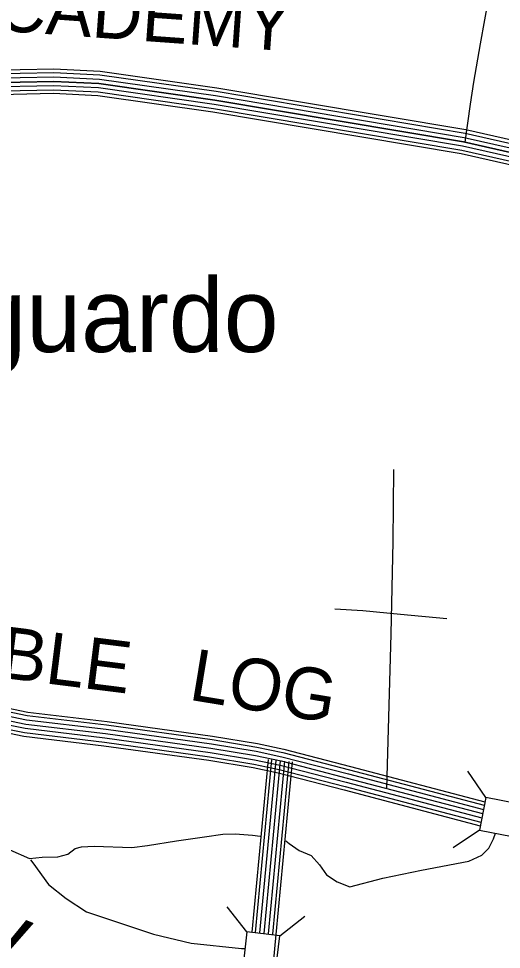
# Model space of a CAD drawing. Extents: x 1788175 to 1969470, y 584502 to 738744.
# Drawn here: x 1840728 to 1844183, y 706761 to 713422 of the extents above; entities that cross this region are included whole.
import ezdxf

# ---------------------------------------------------------------- set-up
doc = ezdxf.new("R2010")
doc.units = 0
for name, color, linetype in [('DESIGN - DRAINAGE - Bridges and Cross Drains Size Text', 7, 'Continuous'), ('DESIGN - ROW - Right-of-Way and Easement Labels', 7, 'Continuous'), ('DESIGN - TRANSPORTATION - Text', 7, 'Continuous'), ('SURVEY - CONTOURS - Index with Text', 7, 'Continuous'), ('SURVEY - DRAINAGE - Storm Sewer', 7, 'Continuous'), ('SURVEY - PROPERTY - Owners', 7, 'Continuous'), ('SURVEY - TRANSPORTATION - Roads', 7, 'Continuous'), ('SURVEY - VEGETATION - Features with Text', 7, 'Continuous')]:
    doc.layers.add(name, color=color, linetype=linetype)

msp = doc.modelspace()

# ---------------------------------------------------------------- linework, layer by layer
at = {"layer": 'DESIGN - TRANSPORTATION - Text'}
for points in [[(1838821.3, 708498.7), (1838866.1, 708397.8), (1838895.5, 708329.2), (1838944.6, 708280.1), (1838993.6, 708231.1), (1839042.6, 708172.3), (1839081.8, 708103.6), (1839130.9, 708064.4), (1839160.3, 707995.8), (1839248.6, 707897.7), (1839307.4, 707829.1), (1839376, 707770.2), (1839493.7, 707750.6), (1839601.6, 707740.8), (1839719.2, 707731), (1839787.9, 707731), (1839886, 707711.4), (1839984, 707691.8), (1840170.3, 707662.4), (1840288, 707623.1), (1840376.3, 707593.7), (1840523.3, 707534.9), (1840805.2, 707412.4)], [(1840805.2, 707412.4), (1840897.8, 707422.3), (1841009.9, 707423.8), (1841079.7, 707442.8), (1841133.3, 707483.5), (1841179.2, 707496.2), (1841269.2, 707499.4), (1841537.6, 707491), (1841649.5, 707504.5), (1841857.3, 707537.4), (1842059.1, 707566.1), (1842189, 707585.9), (1842279, 707587.1), (1842401.2, 707578.8), (1842456.5, 707572.3)], [(1842639.5, 707537.1), (1842664.2, 707518.2), (1842736.9, 707469.1), (1842821.4, 707434.2), (1842880.2, 707366.9), (1842931.2, 707295.5), (1843007.9, 707244.5), (1843098.4, 707209.7), (1843333.8, 707270.9), (1843611.3, 707328.7), (1843950.9, 707391.4), (1844042.4, 707436.7), (1844091.8, 707485.4), (1844127, 707552), (1844141.3, 707592.6)], [(1840812.5, 707403.3), (1840830.9, 707380.3), (1840942.5, 707224.5), (1841069, 707124.5), (1841213.6, 707030.2), (1841422.7, 706961), (1841693.5, 706870.9), (1841962.6, 706804.9), (1842322.3, 706767.5), (1842347.7, 706766.4)]]:
    msp.add_lwpolyline(points, dxfattribs=at)
at = {"layer": 'SURVEY - CONTOURS - Index with Text'}
for points in [[(1851668.5, 710218.1), (1850819.3, 710320.4), (1849678.2, 710418.6), (1849294.4, 710465.2), (1849214.5, 710486.9), (1848774.2, 710696.2), (1846649.5, 711685.6), (1845390.2, 712274.5), (1845152.1, 712348.7), (1843927.8, 712625.5), (1842145.7, 712925.5), (1841311.9, 713044.1), (1840980.8, 713061), (1840496.5, 713049.7), (1840098.4, 713053.4), (1839938.2, 713094.5), (1839681.8, 713179.4), (1839542, 713202.9), (1839378.8, 713217.3), (1838414.2, 713348.6), (1837866.1, 713448.2)], [(1851661.2, 710161.8), (1850813.5, 710264), (1849672.3, 710362.2), (1849283.5, 710409.4), (1849194.7, 710433.5), (1848750, 710644.9), (1846625.5, 711634.2), (1845369.7, 712221.5), (1845137.4, 712293.8), (1843916.8, 712569.8), (1842137, 712869.5), (1841306.5, 712987.6), (1840980, 713004.3), (1840496.9, 712993), (1840091, 712996.8), (1839922.2, 713040.1), (1839668.1, 713124.2), (1839534.8, 713146.6), (1839372.4, 713160.9), (1838405.3, 713292.6), (1837898, 713384.7)], [(1851665.2, 710192.6), (1850816.7, 710294.8), (1849675.5, 710393), (1849289.5, 710439.9), (1849205.5, 710462.7), (1848763.2, 710673), (1846638.6, 711662.3), (1845380.9, 712250.5), (1845145.4, 712323.8), (1843922.8, 712600.3), (1842141.7, 712900.1), (1841309.5, 713018.4), (1840980.4, 713035.3), (1840496.7, 713024), (1840095.1, 713027.7), (1839931, 713069.8), (1839675.6, 713154.3), (1839538.8, 713177.4), (1839375.9, 713191.8), (1838410.1, 713323.2), (1837903.6, 713415.2)], [(1851653.3, 710100.3), (1850807.1, 710202.3), (1849665.9, 710300.5), (1849271.6, 710348.4), (1849173.1, 710375.1), (1848723.6, 710588.8), (1846599.3, 711578), (1845347.2, 712163.6), (1845121.3, 712233.9), (1843904.8, 712509), (1842127.5, 712808.2), (1841300.5, 712925.8), (1840979.1, 712942.2), (1840497.3, 712931), (1840082.9, 712934.8), (1839904.8, 712980.5), (1839653.1, 713063.8), (1839526.9, 713085.1), (1839365.5, 713099.3), (1838395.5, 713231.3), (1837886.9, 713323.7)], [(1837892.5, 713354.2), (1838400.4, 713261.9), (1839369, 713130.1), (1839530.9, 713115.8), (1839660.6, 713094), (1839913.5, 713010.3), (1840086.9, 712965.8), (1840497.1, 712962), (1840979.6, 712973.2), (1841303.5, 712956.7), (1842132.2, 712838.8), (1843910.8, 712539.4), (1845129.4, 712263.9), (1845358.4, 712192.6), (1846612.4, 711606.1), (1848736.8, 710616.9), (1849183.9, 710404.3), (1849277.6, 710378.9), (1849669.1, 710331.4), (1850810.3, 710233.2), (1851657.3, 710131.1)], [(1851657.3, 710131.1), (1850810.3, 710233.2), (1849669.1, 710331.4), (1849277.6, 710378.9), (1849183.9, 710404.3), (1848736.8, 710616.9), (1846612.4, 711606.1), (1845358.4, 712192.6), (1845129.4, 712263.9), (1843910.8, 712539.4), (1842132.2, 712838.8), (1841303.5, 712956.7), (1840979.6, 712973.2), (1840497.1, 712962), (1840086.9, 712965.8), (1839913.5, 713010.3), (1839660.6, 713094), (1839530.9, 713115.8), (1839369, 713130.1), (1838400.4, 713261.9), (1837892.5, 713354.2)], [(1851646.2, 710045.1), (1850801.4, 710146.9), (1849660.2, 710245.1), (1849261, 710293.6), (1849153.7, 710322.6), (1848699.9, 710538.4), (1846575.7, 711527.5), (1845327, 712111.5), (1845106.9, 712180.1), (1843894, 712454.3), (1842118.9, 712753.1), (1841295.2, 712870.3), (1840978.4, 712886.5), (1840497.7, 712875.3), (1840075.6, 712879.2), (1839889.1, 712927), (1839639.7, 713009.6), (1839519.8, 713029.8), (1839359.3, 713043.9), (1838386.8, 713176.3), (1837877, 713268.9)], [(1851649.3, 710069.6), (1850803.9, 710171.5), (1849662.7, 710269.7), (1849265.7, 710317.9), (1849162.3, 710345.9), (1848710.4, 710560.8), (1846586.2, 711549.9), (1845336, 712134.6), (1845113.3, 712203.9), (1843898.8, 712478.6), (1842122.7, 712777.6), (1841297.6, 712894.9), (1840978.7, 712911.2), (1840497.6, 712900), (1840078.8, 712903.9), (1839896.1, 712950.8), (1839645.6, 713033.6), (1839523, 713054.3), (1839362.1, 713068.5), (1838390.7, 713200.7), (1837881.4, 713293.2)]]:
    msp.add_lwpolyline(points, dxfattribs=at)
at = {"layer": 'SURVEY - DRAINAGE - Storm Sewer'}
for p, q in [((1844070.3, 707848), (1843942.6, 708035.8)), ((1844025.9, 707614.6), (1843838.1, 707486.8)), ((1842362, 706886.6), (1842221.5, 707065.1)), ((1842597.9, 706858.5), (1842776.4, 706999))]:
    msp.add_line(p, q, dxfattribs=at)
for points in [[(1844025.9, 707614.6), (1844259.3, 707570.1), (1844303.7, 707803.6), (1844070.3, 707848)], [(1842362, 706886.6), (1842333.9, 706650.7), (1842569.9, 706622.6), (1842597.9, 706858.5)]]:
    msp.add_lwpolyline(points, close=True, dxfattribs=at)
at = {"layer": 'SURVEY - PROPERTY - Owners'}
msp.add_lwpolyline([(1843862.7, 716332.2), (1843865.8, 716268.1), (1843821, 715704), (1843802.3, 715405.8), (1843770.6, 715172), (1843740, 715008.2), (1843717.3, 714708.1), (1843648.7, 714156.3), (1843611.9, 713852.4), (1843605.4, 713820.5), (1843607, 713794.4), (1843636.7, 713776), (1843830.6, 713763.1), (1844038.4, 713738), (1844074.1, 713721.5), (1844095.6, 713683.1), (1844092.1, 713587), (1844030.6, 713241.4), (1843982.3, 712967.8), (1843959.8, 712809.9), (1843921.2, 712537.1)], dxfattribs=at)
msp.add_lwpolyline([(1843862.7, 716332.2), (1843865.8, 716268.1), (1843821, 715704), (1843802.3, 715405.8), (1843770.6, 715172), (1843740, 715008.2), (1843717.3, 714708.1), (1843648.7, 714156.3), (1843611.9, 713852.4), (1843605.4, 713820.5), (1843607, 713794.4), (1843636.7, 713776), (1843830.6, 713763.1), (1844038.4, 713738), (1844074.1, 713721.5), (1844095.6, 713683.1), (1844092.1, 713587), (1844030.6, 713241.4), (1843982.3, 712967.8), (1843959.8, 712809.9), (1843921.2, 712537.1)], dxfattribs=at)
at = {"layer": 'SURVEY - TRANSPORTATION - Roads'}
for points in [[(1843411.8, 710195), (1843407.1, 709680.1), (1843392, 709017.6), (1843360.8, 707913.3)], [(1842991.1, 709198.8), (1843192.4, 709185.7), (1843460, 709160.5), (1843793, 709129.2)], [(1838931.2, 708661.9), (1839317.7, 708616.1), (1839595.2, 708566.2), (1839854.6, 708534.9), (1840162.7, 708522.6), (1840341.3, 708512), (1840525.4, 708488.9), (1840790.5, 708435.1), (1841358, 708367.2), (1842112.2, 708262.3), (1842433.7, 708209.4), (1842620, 708170.2), (1843095.9, 708046.9), (1844060, 707793.8)], [(1838933.6, 708686.5), (1839321.3, 708640.6), (1839598.8, 708590.6), (1839856.6, 708559.6), (1840163.9, 708547.3), (1840343.6, 708536.6), (1840529.4, 708513.3), (1840794.5, 708459.5), (1841361.1, 708391.7), (1842115.9, 708286.7), (1842438.3, 708233.7), (1842625.6, 708194.2), (1843102.1, 708070.8), (1844064.6, 707818.1)], [(1838925, 708600.2), (1839308.5, 708554.8), (1839586, 708504.8), (1839849.6, 708473.1), (1840159.6, 708460.7), (1840335.6, 708450.2), (1840515.3, 708427.6), (1840780.7, 708373.8), (1841350, 708305.7), (1842102.9, 708201), (1842422.3, 708148.4), (1842605.8, 708109.8), (1843080.2, 707986.9), (1844048.4, 707732.7)], [(1838925, 708600.2), (1839308.5, 708554.8), (1839586, 708504.8), (1839849.6, 708473.1), (1840159.6, 708460.7), (1840335.6, 708450.2), (1840515.3, 708427.6), (1840780.7, 708373.8), (1841350, 708305.7), (1842102.9, 708201), (1842422.3, 708148.4), (1842605.8, 708109.8), (1843080.2, 707986.9), (1844048.4, 707732.7)], [(1838928.1, 708631), (1839313.1, 708585.5), (1839590.6, 708535.5), (1839852.1, 708504), (1840161.2, 708491.7), (1840338.4, 708481.1), (1840520.4, 708458.3), (1840785.6, 708404.5), (1841354, 708336.5), (1842107.5, 708231.6), (1842428, 708178.9), (1842612.9, 708140), (1843088.1, 708016.9), (1844054.2, 707763.3)], [(1838918.8, 708538.5), (1839299.4, 708493.4), (1839576.8, 708443.5), (1839844.7, 708411.2), (1840156.6, 708398.8), (1840329.9, 708388.4), (1840505.3, 708366.4), (1840770.8, 708312.6), (1841342, 708244.2), (1842093.6, 708139.7), (1842410.8, 708087.5), (1842591.6, 708049.4), (1843064.6, 707926.9), (1844036.7, 707671.7)], [(1838921.9, 708569.3), (1839304, 708524.1), (1839581.4, 708474.2), (1839847.2, 708442.1), (1840158.1, 708429.7), (1840332.7, 708419.3), (1840510.3, 708397), (1840775.8, 708343.2), (1841346, 708275), (1842098.2, 708170.3), (1842416.6, 708117.9), (1842598.7, 708079.6), (1843072.4, 707956.9), (1844042.5, 707702.2)], [(1838916.3, 708512.9), (1839295.6, 708468), (1839572.9, 708418), (1839842.6, 708385.6), (1840155.3, 708373.1), (1840327.5, 708362.8), (1840501.1, 708341), (1840766.7, 708287.2), (1841338.7, 708218.7), (1842089.7, 708114.2), (1842406.1, 708062.2), (1842585.8, 708024.4), (1843058.1, 707902.1), (1844031.9, 707646.4)], [(1842513.1, 708119.2), (1842396, 706884.1), (1842395.8, 706882.6)], [(1842686.7, 708102.7), (1842569.6, 706867.7), (1842400.7, 705073.8), (1842173.2, 702577.4), (1842066.6, 701489.4), (1842043.3, 701366), (1841986.2, 701272.9), (1841926, 701203.2), (1841758.3, 701042.3), (1841350, 700657.1), (1841100.4, 700353)], [(1842538.7, 708116.8), (1842421.6, 706881.7), (1842421.4, 706879.5)], [(1842569.6, 708113.8), (1842452.4, 706878.7), (1842452.2, 706875.9)], [(1842600.4, 708110.9), (1842483.3, 706875.8), (1842482.9, 706872.2)], [(1842600.4, 708110.9), (1842483.3, 706875.8), (1842482.9, 706872.2)], [(1842631.3, 708108), (1842514.2, 706872.9), (1842513.7, 706868.5)], [(1842662.1, 708105.1), (1842545, 706870), (1842544.5, 706864.9)]]:
    msp.add_lwpolyline(points, dxfattribs=at)

# ---------------------------------------------------------------- texts
at = {"layer": 'DESIGN - DRAINAGE - Bridges and Cross Drains Size Text'}
msp.add_text('Dry', height=475, rotation=338.19971, dxfattribs=at).set_placement((1839785.4, 706977))
at = {"layer": 'DESIGN - ROW - Right-of-Way and Easement Labels'}
for s, rotation, p in [('ACADEMY', 355.90765, (1840230, 713361.7)), ('DOUBLE', 352.8462, (1839491.5, 708844.4)), ('LOG', 350.65408, (1841937.8, 708549.4))]:
    msp.add_text(s, height=370, rotation=rotation, dxfattribs=at).set_placement(p)
at = {"layer": 'SURVEY - VEGETATION - Features with Text'}
msp.add_text('Laguardo', height=528, dxfattribs=at).set_placement((1839604.8, 711036.3))

doc.saveas('drawing.dxf')
